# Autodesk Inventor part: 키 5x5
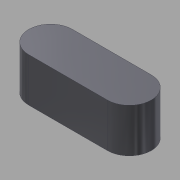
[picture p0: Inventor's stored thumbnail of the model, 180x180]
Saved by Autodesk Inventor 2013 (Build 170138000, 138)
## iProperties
Created: 2014-10
Part Number: 키 5x5
Document SubType Name: Modeling
Designer: KYOUNG IL JANG
Density: 7.86 g/cm^3
Mass: 2.54015 g
Surface Area: 2.9781 cm^2
Volume: 0.323175 cm^3
Material: 강철, 연강
d0: 5.000 mm
d1: 14.000 mm
d2: 5.000 mm
d3: 0.00 deg
Author: SeoGD™ [www.esajin.kr]
Revision Number: 1
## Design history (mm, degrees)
sketch "스케치1"
  geometry: L1 (-4.5, -2.5)-(4.5, -2.5); L2 (4.5, 2.5)-(-4.5, 2.5); A1 r 2.5 centre (4.5, 0) between (4.5, -2.5) and (4.5, 2.5); A2 r 2.5 centre (-4.5, 0) between (-4.5, 2.5) and (-4.5, -2.5); 2 further points
  constraints: 4 end point, 4 point on circle, 4 tangent, 2 centre point, 1 horizontal, 1 horizontal alignment, 1 midpoint, 1 parallel, 1 vertical alignment
  dimensions: "d0" = 5 distance between parallel lines of L1 L2; "d1" = 14 dimension on A1 A2
extrude "돌출1" new body sketch "스케치1" stored distance "d2" = 5; taper "d3" = 0 deg
node "솔리드1"
